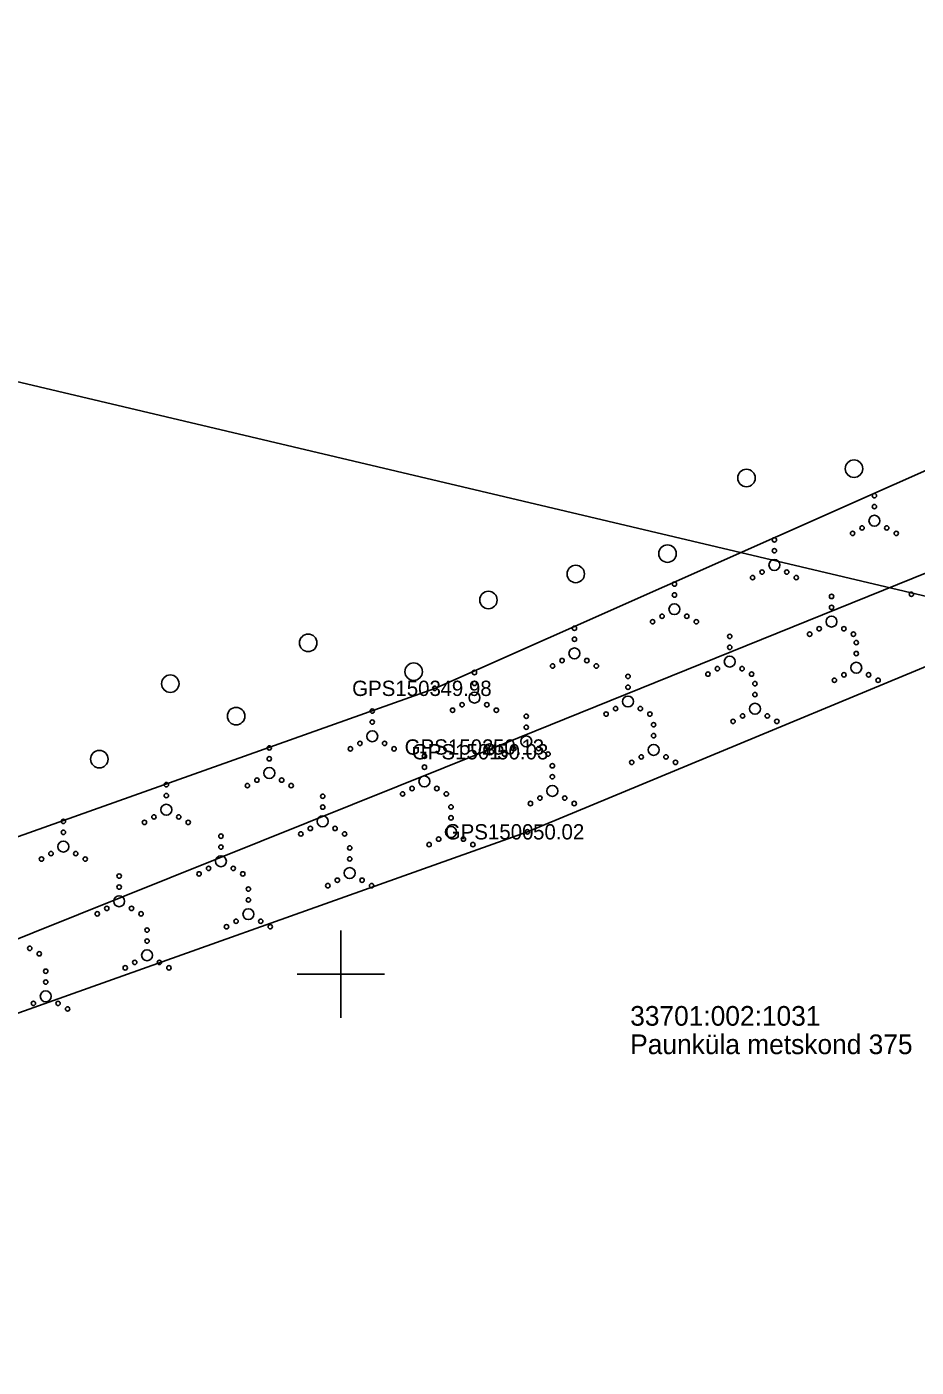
# Model space of a CAD drawing. Extents: x 551623 to 559850, y 6561220 to 6567135.
# Drawn here: x 556585.6 to 556626.3, y 6565132 to 6565193.3 of the extents above; entities that cross this region are included whole.
import ezdxf

# ---------------------------------------------------------------- set-up
doc = ezdxf.new("R2010")
doc.units = 0
for name, color, linetype in [('HALJASTUS', 7, 'Continuous'), ('KORGUS-EH2000', 7, 'Continuous'), ('KPOHULIIN', 7, 'Continuous'), ('MOOTKORG-EH2000', 7, 'Continuous'), ('MOOTMPUNKT', 7, 'Continuous'), ('MOOTNR', 7, 'Continuous'), ('MOOTPIIR', 7, 'Continuous'), ('MPOHULIIN', 7, 'Continuous'), ('PIIR', 7, 'Continuous'), ('POST', 7, 'Continuous'), ('VORK', 7, 'Continuous')]:
    doc.layers.add(name, color=color, linetype=linetype)

msp = doc.modelspace()

# ---------------------------------------------------------------- linework, layer by layer
at = {"layer": 'HALJASTUS'}
msp.add_lwpolyline([(556560.214, 6565152.796), (556566.555, 6565150.865), (556570.04, 6565150.556), (556579.273, 6565154.176), (556604.291, 6565163.073), (556630.484, 6565174.696), (556655.692, 6565185.071), (556676.45, 6565195.172), (556699.828, 6565206.048), (556722.286, 6565214.456), (556752.299, 6565224.302), (556776.314, 6565234.412), (556799.911, 6565243.207), (556817.364, 6565249.633), (556836.836, 6565258.911)], dxfattribs=at)
for centre, radius in [((556623.464, 6565173.12), 0.4), ((556618.546, 6565172.694), 0.4), ((556624.398, 6565171.887), 0.1), ((556624.398, 6565171.387), 0.1), ((556624.398, 6565170.737), 0.25), ((556623.398, 6565170.162), 0.1), ((556623.833, 6565170.412), 0.1), ((556624.963, 6565170.412), 0.1), ((556625.398, 6565170.162), 0.1), ((556614.934, 6565169.236), 0.4), ((556619.825, 6565169.865), 0.1), ((556619.825, 6565169.365), 0.1), ((556619.825, 6565168.715), 0.25), ((556610.739, 6565168.306), 0.4), ((556618.825, 6565168.14), 0.1), ((556619.26, 6565168.39), 0.1), ((556620.39, 6565168.39), 0.1), ((556620.825, 6565168.14), 0.1), ((556615.253, 6565167.843), 0.1), ((556606.745, 6565167.112), 0.4), ((556615.253, 6565167.343), 0.1), ((556622.436, 6565167.276), 0.1), ((556626.09, 6565167.378), 0.1), ((556614.688, 6565166.368), 0.1), ((556615.253, 6565166.693), 0.25), ((556615.818, 6565166.368), 0.1), ((556622.436, 6565166.776), 0.1), ((556610.68, 6565165.82), 0.1), ((556614.253, 6565166.118), 0.1), ((556616.253, 6565166.118), 0.1), ((556621.871, 6565165.801), 0.1), ((556622.436, 6565166.126), 0.25), ((556623.001, 6565165.801), 0.1), ((556598.504, 6565165.152), 0.4), ((556610.68, 6565165.32), 0.1), ((556617.782, 6565165.448), 0.1), ((556621.436, 6565165.551), 0.1), ((556623.436, 6565165.551), 0.1), ((556623.568, 6565165.165), 0.1), ((556610.68, 6565164.67), 0.25), ((556617.782, 6565164.948), 0.1), ((556623.568, 6565164.665), 0.1), ((556603.328, 6565163.835), 0.4), ((556609.68, 6565164.095), 0.1), ((556610.115, 6565164.345), 0.1), ((556611.245, 6565164.345), 0.1), ((556611.68, 6565164.095), 0.1), ((556617.217, 6565163.973), 0.1), ((556617.782, 6565164.298), 0.25), ((556618.347, 6565163.973), 0.1), ((556623.568, 6565164.015), 0.25), ((556592.195, 6565163.284), 0.4), ((556606.107, 6565163.798), 0.1), ((556606.107, 6565163.298), 0.1), ((556613.128, 6565163.621), 0.1), ((556616.782, 6565163.723), 0.1), ((556618.782, 6565163.723), 0.1), ((556618.935, 6565163.287), 0.1), ((556622.568, 6565163.44), 0.1), ((556623.003, 6565163.69), 0.1), ((556624.133, 6565163.69), 0.1), ((556624.568, 6565163.44), 0.1), ((556606.107, 6565162.648), 0.25), ((556613.128, 6565162.471), 0.25), ((556613.128, 6565163.121), 0.1), ((556618.935, 6565162.787), 0.1), ((556595.206, 6565161.801), 0.4), ((556601.432, 6565162.031), 0.1), ((556605.107, 6565162.073), 0.1), ((556605.542, 6565162.323), 0.1), ((556606.672, 6565162.323), 0.1), ((556607.107, 6565162.073), 0.1), ((556612.563, 6565162.146), 0.1), ((556613.693, 6565162.146), 0.1), ((556618.935, 6565162.137), 0.25), ((556601.432, 6565161.531), 0.1), ((556608.474, 6565161.793), 0.1), ((556612.128, 6565161.896), 0.1), ((556614.128, 6565161.896), 0.1), ((556614.301, 6565161.408), 0.1), ((556617.935, 6565161.562), 0.1), ((556618.37, 6565161.812), 0.1), ((556619.5, 6565161.812), 0.1), ((556619.935, 6565161.562), 0.1), ((556601.432, 6565160.881), 0.25), ((556608.474, 6565160.643), 0.25), ((556608.474, 6565161.293), 0.1), ((556614.301, 6565160.908), 0.1), ((556596.724, 6565160.349), 0.1), ((556600.432, 6565160.306), 0.1), ((556600.867, 6565160.556), 0.1), ((556601.997, 6565160.556), 0.1), ((556602.432, 6565160.306), 0.1), ((556607.909, 6565160.318), 0.1), ((556609.039, 6565160.318), 0.1), ((556614.301, 6565160.258), 0.25), ((556588.953, 6565159.834), 0.4), ((556596.724, 6565159.849), 0.1), ((556603.82, 6565159.966), 0.1), ((556607.474, 6565160.068), 0.1), ((556609.474, 6565160.068), 0.1), ((556613.301, 6565159.683), 0.1), ((556613.736, 6565159.933), 0.1), ((556614.866, 6565159.933), 0.1), ((556615.301, 6565159.683), 0.1), ((556596.724, 6565159.199), 0.25), ((556603.82, 6565158.816), 0.25), ((556603.82, 6565159.466), 0.1), ((556609.668, 6565159.529), 0.1), ((556609.668, 6565159.029), 0.1), ((556592.015, 6565158.667), 0.1), ((556595.724, 6565158.624), 0.1), ((556596.159, 6565158.874), 0.1), ((556597.289, 6565158.874), 0.1), ((556597.724, 6565158.624), 0.1), ((556603.255, 6565158.491), 0.1), ((556604.385, 6565158.491), 0.1), ((556609.668, 6565158.379), 0.25), ((556592.015, 6565158.167), 0.1), ((556599.166, 6565158.138), 0.1), ((556602.82, 6565158.241), 0.1), ((556604.82, 6565158.241), 0.1), ((556608.668, 6565157.804), 0.1), ((556609.103, 6565158.054), 0.1), ((556610.233, 6565158.054), 0.1), ((556610.668, 6565157.804), 0.1), ((556591.45, 6565157.192), 0.1), ((556592.015, 6565157.517), 0.25), ((556592.58, 6565157.192), 0.1), ((556599.166, 6565156.988), 0.25), ((556599.166, 6565157.638), 0.1), ((556605.034, 6565157.65), 0.1), ((556605.034, 6565157.15), 0.1), ((556587.306, 6565156.986), 0.1), ((556591.015, 6565156.942), 0.1), ((556593.015, 6565156.942), 0.1), ((556598.601, 6565156.663), 0.1), ((556599.731, 6565156.663), 0.1), ((556605.034, 6565156.5), 0.25), ((556587.306, 6565155.836), 0.25), ((556587.306, 6565156.486), 0.1), ((556594.512, 6565156.311), 0.1), ((556598.166, 6565156.413), 0.1), ((556600.166, 6565156.413), 0.1), ((556604.034, 6565155.925), 0.1), ((556604.469, 6565156.175), 0.1), ((556605.599, 6565156.175), 0.1), ((556606.034, 6565155.925), 0.1), ((556586.306, 6565155.261), 0.1), ((556586.741, 6565155.511), 0.1), ((556587.871, 6565155.511), 0.1), ((556588.306, 6565155.261), 0.1), ((556594.512, 6565155.161), 0.25), ((556594.512, 6565155.811), 0.1), ((556600.401, 6565155.771), 0.1), ((556600.401, 6565155.271), 0.1), ((556593.947, 6565154.836), 0.1), ((556595.077, 6565154.836), 0.1), ((556600.401, 6565154.621), 0.25), ((556589.858, 6565154.483), 0.1), ((556593.512, 6565154.586), 0.1), ((556595.512, 6565154.586), 0.1), ((556599.401, 6565154.046), 0.1), ((556599.836, 6565154.296), 0.1), ((556600.966, 6565154.296), 0.1), ((556601.401, 6565154.046), 0.1), ((556589.858, 6565153.333), 0.25), ((556589.858, 6565153.983), 0.1), ((556595.767, 6565153.892), 0.1), ((556589.293, 6565153.008), 0.1), ((556590.423, 6565153.008), 0.1), ((556595.767, 6565152.742), 0.25), ((556595.767, 6565153.392), 0.1), ((556588.858, 6565152.758), 0.1), ((556590.858, 6565152.758), 0.1), ((556595.202, 6565152.417), 0.1), ((556596.332, 6565152.417), 0.1), ((556591.134, 6565152.013), 0.1), ((556594.767, 6565152.167), 0.1), ((556596.767, 6565152.167), 0.1), ((556585.769, 6565151.18), 0.1), ((556591.134, 6565150.863), 0.25), ((556591.134, 6565151.513), 0.1), ((556586.204, 6565150.93), 0.1), ((556590.569, 6565150.538), 0.1), ((556591.699, 6565150.538), 0.1), ((556586.5, 6565150.134), 0.1), ((556590.134, 6565150.288), 0.1), ((556592.134, 6565150.288), 0.1), ((556586.5, 6565148.984), 0.25), ((556586.5, 6565149.634), 0.1), ((556585.935, 6565148.659), 0.1), ((556587.065, 6565148.659), 0.1), ((556587.5, 6565148.409), 0.1)]:
    msp.add_circle(centre, radius, dxfattribs=at)
at = {"layer": 'KORGUS-EH2000'}
for centre in [(556604.291, 6565163.073), (556606.884, 6565160.173), (556608.526, 6565156.509)]:
    msp.add_circle(centre, 0.1, dxfattribs=at)
at = {"layer": 'KPOHULIIN'}
msp.add_lwpolyline([(556534.631, 6565146.039), (556550.784, 6565137.989), (556573.361, 6565146.85), (556606.789, 6565160.281), (556655.904, 6565180.147), (556702.486, 6565198.719), (556702.486, 6565198.719), (556755.324, 6565220.022), (556800.207, 6565237.954), (556845.124, 6565255.757), (556845.124, 6565255.757), (556885.115, 6565272.075)], dxfattribs=at)
at = {"layer": 'MOOTMPUNKT'}
for centre in [(556604.291, 6565163.073), (556606.693, 6565160.389), (556606.884, 6565160.173), (556608.526, 6565156.509)]:
    msp.add_circle(centre, 0.1, dxfattribs=at)
at = {"layer": 'MOOTPIIR'}
for points in [[(556752.299, 6565224.302), (556722.286, 6565214.456), (556699.828, 6565206.048), (556676.45, 6565195.172), (556655.692, 6565185.071), (556630.484, 6565174.696), (556604.291, 6565163.073), (556579.273, 6565154.176), (556570.04, 6565150.556), (556566.682, 6565150.593), (556559.96, 6565151.833), (556559.005, 6565148.531), (556554.988, 6565148.026), (556532.572, 6565157.699), (556503.633, 6565171.674), (556471.481, 6565186.145), (556450.892, 6565195.194), (556444.303, 6565198.685), (556419.033, 6565208.861)], [(556436.48, 6565194.185), (556449.647, 6565188.215), (556486.494, 6565172.264), (556501.317, 6565164.974), (556534.661, 6565148.753), (556550.886, 6565142.039), (556560.868, 6565140.849), (556563.777, 6565138.667), (556564.947, 6565140.416), (556574.124, 6565143.095), (556582.549, 6565147.264), (556608.526, 6565156.509), (556634.616, 6565167.336), (556657.454, 6565177.431), (556678.781, 6565185.856), (556704.754, 6565195.238), (556727.607, 6565205.59), (556758.128, 6565217.782)]]:
    msp.add_lwpolyline(points, dxfattribs=at)
at = {"layer": 'MPOHULIIN'}
msp.add_lwpolyline([(556571.75, 6565140.835), (556573.361, 6565146.85), (556606.789, 6565160.281), (556655.904, 6565180.147), (556702.486, 6565198.719), (556755.324, 6565220.022), (556755.324, 6565220.022), (556800.207, 6565237.954), (556845.124, 6565255.757), (556885.115, 6565272.075), (556885.115, 6565272.075)], dxfattribs=at)
at = {"layer": 'PIIR'}
for points in [[(556570.09, 6565180.67), (556591.74, 6565273.2), (556848.22, 6565213.26), (556849.69, 6565182.56), (556886.74, 6565191.59), (556924.89, 6565200.89), (556960.45, 6565209.56), (557008.05, 6565221.16), (557063.92, 6565234.78), (557142.45, 6565253.92), (557149.85, 6565228.01), (557118.41, 6565095.6), (557117.08, 6565090.14), (557111.29, 6565052.74)], [(556570.09, 6565180.67), (557111.29, 6565052.74), (557117.08, 6565090.14), (557118.41, 6565095.6), (557901.49, 6564929.97), (557785.81, 6564832.39), (557095.9, 6564977.82), (557081.84, 6564912.06), (557074.86, 6564913.78), (556985.4, 6564932.84), (556549.21, 6565025.4), (556543.91, 6565008.61), (556523.04, 6565015.28), (556518.27, 6565016.8), (556561.87, 6565145.74)]]:
    msp.add_lwpolyline(points, close=True, dxfattribs=at)
at = {"layer": 'POST'}
msp.add_circle((556606.789, 6565160.281), 0.25, dxfattribs=at)
at = {"layer": 'VORK'}
for p, q in [((556600, 6565152), (556600, 6565148)), ((556598, 6565150), (556602, 6565150))]:
    msp.add_line(p, q, dxfattribs=at)

# ---------------------------------------------------------------- texts
at = {"layer": 'KORGUS-EH2000'}
for s, p in [(' 49.98', (556604.291, 6565162.723)), (' 50.03', (556606.884, 6565159.822)), (' 50.02', (556608.526, 6565156.159))]:
    msp.add_text(s, height=0.7, dxfattribs=at).set_placement(p)
at = {"layer": 'MOOTKORG-EH2000'}
for s, p in [(' 49.98', (556604.291, 6565162.723)), (' 50.13', (556606.693, 6565160.039)), (' 50.03', (556606.884, 6565159.822)), (' 50.02', (556608.526, 6565156.159))]:
    msp.add_text(s, height=0.7, dxfattribs=at).set_placement(p)
at = {"layer": 'MOOTNR'}
for s, p in [('GPS1503 ', (556600.512, 6565162.723)), ('GPS1502 ', (556602.914, 6565160.039)), ('GPS1501 ', (556603.244, 6565159.822)), ('GPS1500 ', (556604.746, 6565156.159))]:
    msp.add_text(s, height=0.7, dxfattribs=at).set_placement(p)
at = {"layer": 'PIIR'}
for s, p in [('33701:002:1031', (556613.229, 6565147.64)), ('Paunküla metskond 375', (556613.229, 6565146.34))]:
    msp.add_text(s, height=0.9, dxfattribs=at).set_placement(p)

doc.saveas('drawing.dxf')
